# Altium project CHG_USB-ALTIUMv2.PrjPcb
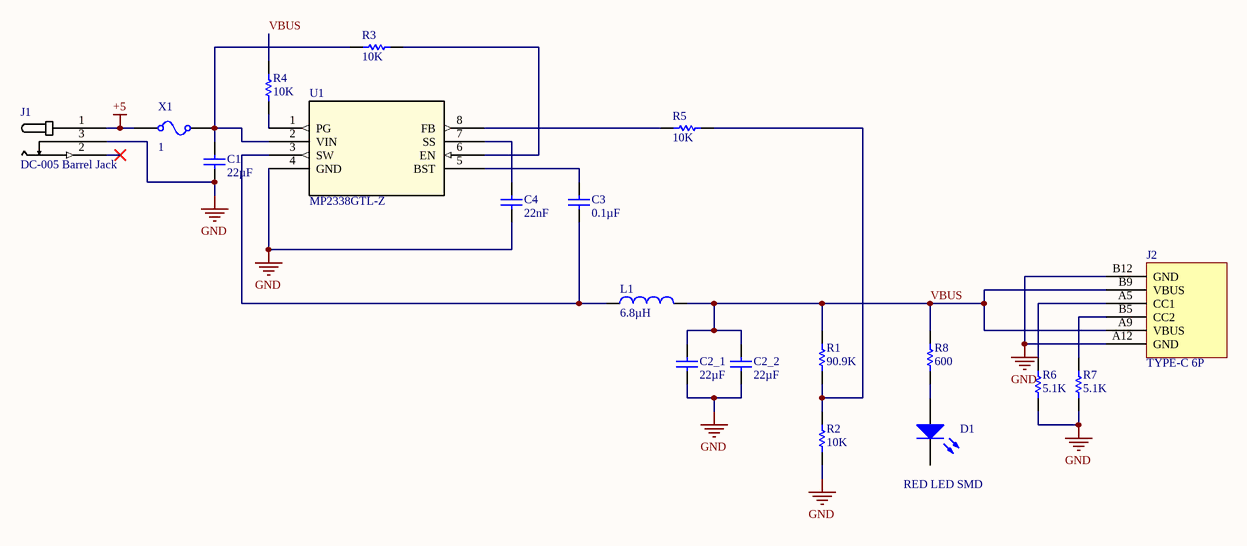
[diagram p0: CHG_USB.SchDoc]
1 sheet, 19 parts. Net scope: global (net labels, ports and power ports of the same name join across sheets).
Board file: CHG_USB.PcbDoc

## Sheet CHG_USB.SchDoc
size A; SheetNumber: 1; SheetTotal: 1

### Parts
C1  value 22µF  (hidden comment: Capacitor)
C2_1  value 22µF  (hidden comment: Capacitor)
C2_2  value 22µF  (hidden comment: Capacitor)
C3  value 0.1µF  (hidden comment: Capacitor)
C4  value 22nF  (hidden comment: Capacitor)
D1  RED LED SMD
J1  DC-005 Barrel Jack
J2  TYPE-C 6P
L1  value 6.8µH  (hidden comment: Inductor)
R1  value 90.9K  (hidden comment: Resistor)
R2  value 10K  (hidden comment: Resistor)
R3  value 10K  (hidden comment: Resistor)
R4  value 10K  (hidden comment: Resistor)
R5  value 10K  (hidden comment: Resistor)
R6  value 5.1K  (hidden comment: Resistor)
R7  value 5.1K  (hidden comment: Resistor)
R8  value 600  (hidden comment: Resistor)
U1  MP2338GTL-Z
X1  CURRENT: 1  (hidden comment: Fuse)

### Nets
+5: J1.1(VIN) X1.1
GND: C1.1 C2_1.1 C2_2.1 C4.1 J1.3(GND) J2.A12(GND) J2.B12(GND) R2.1 R6.1 R7.1 U1.4(GND)
VBUS: C2_1.2 C2_2.2 J2.A9(VBUS) J2.B9(VBUS) L1.2 R1.2 R4.2 R8.2
NetC1_2: C1.2 R3.1 U1.2(VIN) X1.2
NetC3_1: C3.1 L1.1 U1.3(SW)
NetC3_2: C3.2 U1.5(BST)
NetC4_2: C4.2 U1.7(SS)
NetD1_1: D1.1(A) R8.1
NetJ2_A5: J2.A5(CC1) R6.2
NetJ2_B5: J2.B5(CC2) R7.2
NetR1_1: R1.1 R2.2 R5.2
NetR3_2: R3.2 U1.6(EN)
NetR4_1: R4.1 U1.1(PG)
NetR5_1: R5.1 U1.8(FB)

Not connected (* = marked no-connect by the designer): D1 2(K); J1 2(SW)*

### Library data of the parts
C1 C2_1 C2_2 C3 C4 = Capacitor: SimulationGenericComponent: True
D1 = LED: Light-Emitting Diode; AF: 1; BV: 0; BV_MAX: 1e99; EG: 1.11; FC: 0.5; IBV: 0.001; IS: 1e-14; MJSW: 0.33; NTUN: 30; TNOM: 27; XTI: 3; SimulationGenericComponent: True
J1 = DC-005 Barrel Jack: Barrel Jack to simplify PCB complexity
L1 = Inductor: SimulationGenericComponent: True
R1-R8 = Resistor: TC1: 0; SimulationGenericComponent: True
U1 = MP2338GTL-Z: MP2338 IC
X1 = Fuse: RESISTANCE: 1m; SimulationGenericComponent: True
